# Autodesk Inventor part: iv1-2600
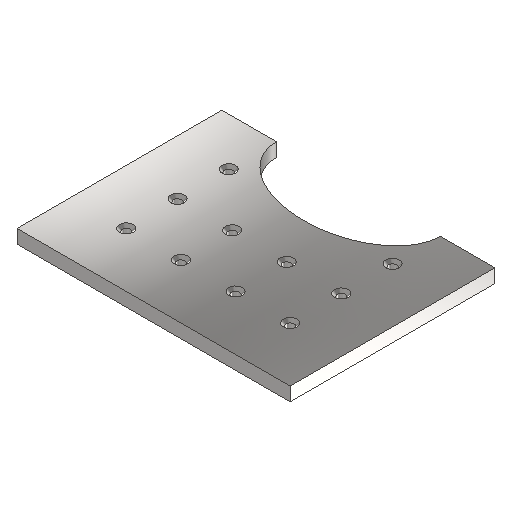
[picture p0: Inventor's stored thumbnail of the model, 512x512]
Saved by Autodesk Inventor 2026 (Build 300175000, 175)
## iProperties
Created: 2004-09
Part Number: iv1-2600
Document SubType Name: Modeling
Designer: Lars Bertram Pedersen
Manufacturer: Standard
Standards Organization: Custom
Material: Steel, Mild
Density: 7.85 g/cm^3
Appearance: Semi-Polished
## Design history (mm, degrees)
sketch "Sketch1" dims "d23" = 20, "d24" = 30
  geometry: L1 (-50, 0)-(50, 0); L2 (50, 0)-(50, 75); L3 (-50, 75)-(-50, 0); L4 (50, 75)-(30, 75); L5 (-30, 75)-(-50, 75); 3 further points; 1 other entity
  constraints: 10 end point, 3 parallel, 1 coincident, 1 collinear, 1 horizontal, 1 horizontal alignment, 1 midpoint, 1 perpendicular, 1 vertical alignment, 4 other
  dimensions: "d0" = 100 distance of L1.start L1.end; "d1" = 75 distance of L3.start L1.start
extrude "Extrusion1" new body sketch "Sketch1" distance "d6" = 5; taper "d7" = 0 deg
sketch "Sketch2"
  geometry: L1 (50, 0)-(-50, 0) reference; L2 (-50, 0)-(-50, 75) reference; 1 further point
  dimensions: "d8" = 20 distance from line of L1 point (-30, 20); "d9" = 20 distance from line of L2 point (-30, 20)
hole "Hole1" sketch "Sketch2" diameter "d10" = 3; stored, may be unused: countersink angle "d14" = 90 deg, drill point angle "d16" = 118 deg; dims "d11" = 6, "d12" = 5, "d13" = 2, "d15" = 5
pattern_linear "Rectangular Pattern1" dims "d22" = 18.75
body "Solid1"
